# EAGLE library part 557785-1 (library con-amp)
AMP connector
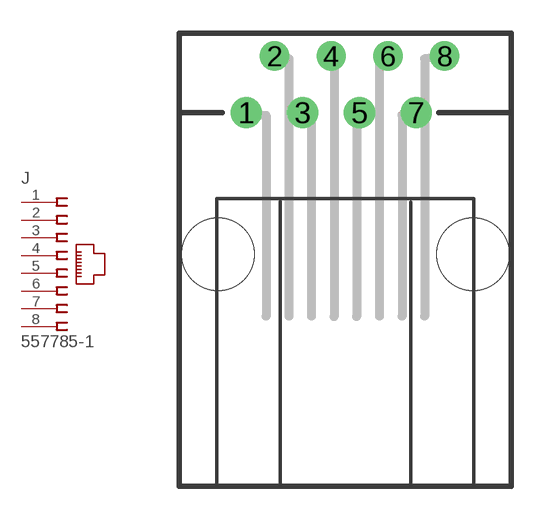
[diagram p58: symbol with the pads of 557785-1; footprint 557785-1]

Designator prefix J

## 557785-1 (MF: TYCO ELECTRONICS; MPN: 5557785-1; OC_FARNELL: 1557723; OC_NEWARK: 42K8768)  [557785-1]
1  1  pas
2  2  pas
3  3  pas
4  4  pas
5  5  pas
6  6  pas
7  7  pas
8  8  pas

## Footprint 557785-1 (pad centres in mm)
Modular Jack
drill 0.889 round: 1 -4.445,6.35; 3 -1.905,6.35; 5 0.635,6.35; 7 3.175,6.35
drill 0.813 round: 2 -3.175,8.89; 4 -0.635,8.89; 6 1.905,8.89; 8 4.445,8.89
hole 3.251 at -5.715,0
hole 3.251 at 5.715,0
